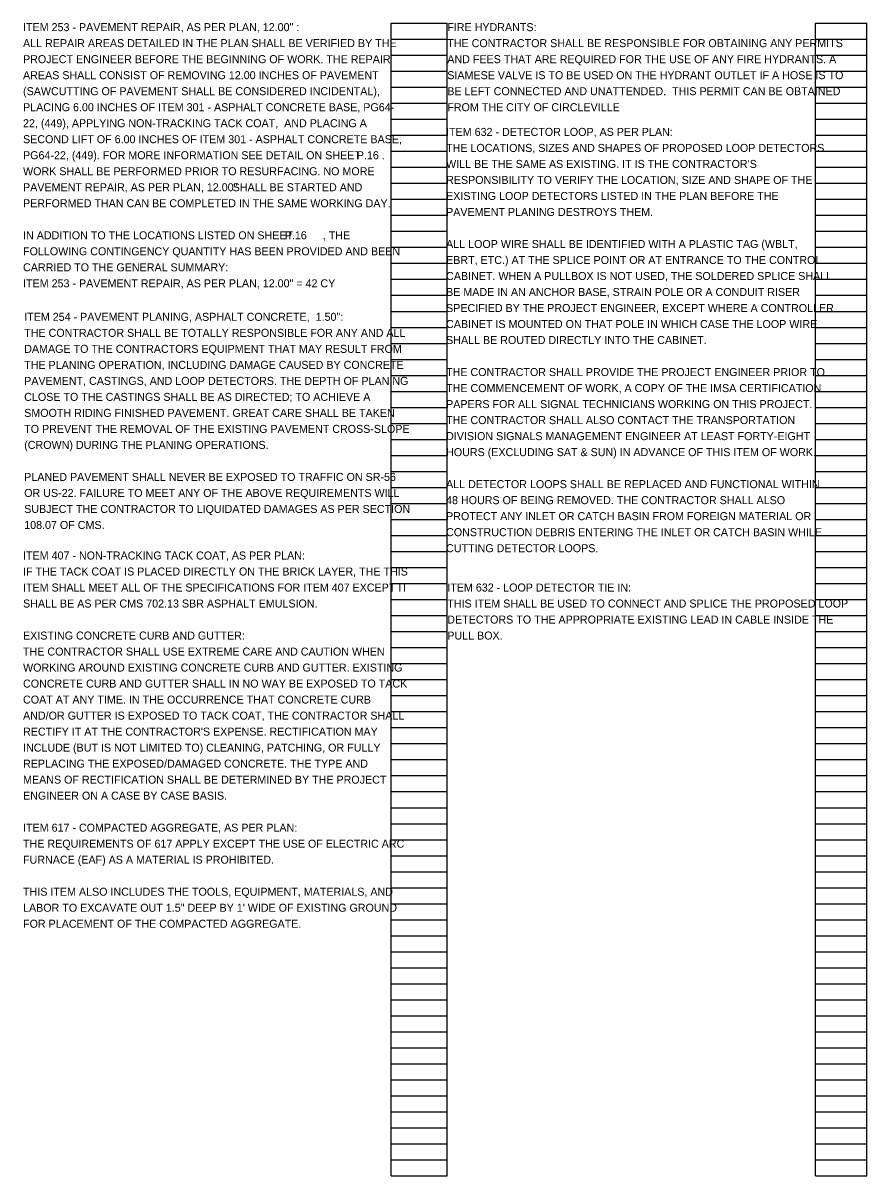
# Model space of a CAD drawing. Extents: x 28776.5 to 28808.5, y 9178.8 to 9230.7.
# Drawn here: x 28793.77 to 28808.53, y 9210.58 to 9230.74 of the extents above; entities that cross this region are included whole.
import ezdxf

# ---------------------------------------------------------------- set-up
doc = ezdxf.new("R2010")
doc.units = 0
for name, color, linetype in [('Default', 7, 'Continuous'), ('SH_Data', 7, 'Continuous'), ('SH_Text', 7, 'Continuous')]:
    doc.layers.add(name, color=color, linetype=linetype)

msp = doc.modelspace()

# ---------------------------------------------------------------- linework, layer by layer
at = {"layer": 'SH_Data'}
for p, q in [((28800.209, 9210.582), (28800.209, 9230.742)), ((28800.209, 9230.742), (28801.189, 9230.742)), ((28801.189, 9210.582), (28801.189, 9230.742)), ((28807.629, 9210.582), (28807.629, 9230.742)), ((28807.629, 9230.742), (28808.529, 9230.742)), ((28808.529, 9210.582), (28808.529, 9230.742)), ((28800.209, 9230.462), (28801.189, 9230.462)), ((28807.629, 9230.462), (28808.529, 9230.462)), ((28800.209, 9230.182), (28801.189, 9230.182)), ((28807.629, 9230.182), (28808.529, 9230.182)), ((28800.209, 9229.902), (28801.189, 9229.902)), ((28807.629, 9229.902), (28808.529, 9229.902)), ((28800.209, 9229.622), (28801.189, 9229.622)), ((28807.629, 9229.622), (28808.529, 9229.622)), ((28800.209, 9229.342), (28801.189, 9229.342)), ((28807.629, 9229.342), (28808.529, 9229.342)), ((28800.209, 9229.062), (28801.189, 9229.062)), ((28807.629, 9229.062), (28808.529, 9229.062)), ((28800.209, 9228.782), (28801.189, 9228.782)), ((28807.629, 9228.782), (28808.529, 9228.782)), ((28800.209, 9228.502), (28801.189, 9228.502)), ((28807.629, 9228.502), (28808.529, 9228.502)), ((28800.209, 9228.222), (28801.189, 9228.222)), ((28807.629, 9228.222), (28808.529, 9228.222)), ((28800.209, 9227.942), (28801.189, 9227.942)), ((28807.629, 9227.942), (28808.529, 9227.942)), ((28800.209, 9227.662), (28801.189, 9227.662)), ((28807.629, 9227.662), (28808.529, 9227.662)), ((28800.209, 9227.382), (28801.189, 9227.382)), ((28807.629, 9227.382), (28808.529, 9227.382)), ((28800.209, 9227.102), (28801.189, 9227.102)), ((28807.629, 9227.102), (28808.529, 9227.102)), ((28800.209, 9226.822), (28801.189, 9226.822)), ((28807.629, 9226.822), (28808.529, 9226.822)), ((28800.209, 9226.542), (28801.189, 9226.542)), ((28807.629, 9226.542), (28808.529, 9226.542)), ((28800.209, 9226.262), (28801.189, 9226.262)), ((28807.629, 9226.262), (28808.529, 9226.262)), ((28800.209, 9225.982), (28801.189, 9225.982)), ((28807.629, 9225.982), (28808.529, 9225.982)), ((28800.209, 9225.702), (28801.189, 9225.702)), ((28807.629, 9225.702), (28808.529, 9225.702)), ((28800.209, 9225.422), (28801.189, 9225.422)), ((28807.629, 9225.422), (28808.529, 9225.422)), ((28800.209, 9225.142), (28801.189, 9225.142)), ((28807.629, 9225.142), (28808.529, 9225.142)), ((28800.209, 9224.862), (28801.189, 9224.862)), ((28807.629, 9224.862), (28808.529, 9224.862)), ((28800.209, 9224.582), (28801.189, 9224.582)), ((28807.629, 9224.582), (28808.529, 9224.582)), ((28800.209, 9224.302), (28801.189, 9224.302)), ((28807.629, 9224.302), (28808.529, 9224.302)), ((28800.209, 9224.022), (28801.189, 9224.022)), ((28807.629, 9224.022), (28808.529, 9224.022)), ((28800.209, 9223.742), (28801.189, 9223.742)), ((28807.629, 9223.742), (28808.529, 9223.742)), ((28800.209, 9223.462), (28801.189, 9223.462)), ((28807.629, 9223.462), (28808.529, 9223.462)), ((28800.209, 9223.182), (28801.189, 9223.182)), ((28807.629, 9223.182), (28808.529, 9223.182)), ((28800.209, 9222.902), (28801.189, 9222.902)), ((28807.629, 9222.902), (28808.529, 9222.902)), ((28800.209, 9222.622), (28801.189, 9222.622)), ((28807.629, 9222.622), (28808.529, 9222.622)), ((28800.209, 9222.342), (28801.189, 9222.342)), ((28807.629, 9222.342), (28808.529, 9222.342)), ((28800.209, 9222.062), (28801.189, 9222.062)), ((28807.629, 9222.062), (28808.529, 9222.062)), ((28800.209, 9221.782), (28801.189, 9221.782)), ((28807.629, 9221.782), (28808.529, 9221.782)), ((28800.209, 9221.502), (28801.189, 9221.502)), ((28807.629, 9221.502), (28808.529, 9221.502)), ((28800.209, 9221.222), (28801.189, 9221.222)), ((28807.629, 9221.222), (28808.529, 9221.222)), ((28800.209, 9220.942), (28801.189, 9220.942)), ((28807.629, 9220.942), (28808.529, 9220.942)), ((28800.209, 9220.662), (28801.189, 9220.662)), ((28807.629, 9220.662), (28808.529, 9220.662)), ((28800.209, 9220.382), (28801.189, 9220.382)), ((28807.629, 9220.382), (28808.529, 9220.382)), ((28800.209, 9220.102), (28801.189, 9220.102)), ((28807.629, 9220.102), (28808.529, 9220.102)), ((28800.209, 9219.822), (28801.189, 9219.822)), ((28807.629, 9219.822), (28808.529, 9219.822)), ((28800.209, 9219.542), (28801.189, 9219.542)), ((28807.629, 9219.542), (28808.529, 9219.542)), ((28800.209, 9219.262), (28801.189, 9219.262)), ((28807.629, 9219.262), (28808.529, 9219.262)), ((28800.209, 9218.982), (28801.189, 9218.982)), ((28807.629, 9218.982), (28808.529, 9218.982)), ((28800.209, 9218.702), (28801.189, 9218.702)), ((28807.629, 9218.702), (28808.529, 9218.702)), ((28800.209, 9218.422), (28801.189, 9218.422)), ((28807.629, 9218.422), (28808.529, 9218.422)), ((28800.209, 9218.142), (28801.189, 9218.142)), ((28807.629, 9218.142), (28808.529, 9218.142)), ((28800.209, 9217.862), (28801.189, 9217.862)), ((28807.629, 9217.862), (28808.529, 9217.862)), ((28800.209, 9217.582), (28801.189, 9217.582)), ((28807.629, 9217.582), (28808.529, 9217.582)), ((28800.209, 9217.302), (28801.189, 9217.302)), ((28807.629, 9217.302), (28808.529, 9217.302)), ((28800.209, 9217.022), (28801.189, 9217.022)), ((28807.629, 9217.022), (28808.529, 9217.022)), ((28800.209, 9216.742), (28801.189, 9216.742)), ((28807.629, 9216.742), (28808.529, 9216.742)), ((28800.209, 9216.462), (28801.189, 9216.462)), ((28807.629, 9216.462), (28808.529, 9216.462)), ((28800.209, 9216.182), (28801.189, 9216.182)), ((28807.629, 9216.182), (28808.529, 9216.182)), ((28800.209, 9215.902), (28801.189, 9215.902)), ((28807.629, 9215.902), (28808.529, 9215.902)), ((28800.209, 9215.622), (28801.189, 9215.622)), ((28807.629, 9215.622), (28808.529, 9215.622)), ((28800.209, 9215.342), (28801.189, 9215.342)), ((28807.629, 9215.342), (28808.529, 9215.342)), ((28800.209, 9215.062), (28801.189, 9215.062)), ((28807.629, 9215.062), (28808.529, 9215.062)), ((28800.209, 9214.782), (28801.189, 9214.782)), ((28807.629, 9214.782), (28808.529, 9214.782)), ((28800.209, 9214.502), (28801.189, 9214.502)), ((28807.629, 9214.502), (28808.529, 9214.502)), ((28800.209, 9214.222), (28801.189, 9214.222)), ((28807.629, 9214.222), (28808.529, 9214.222)), ((28800.209, 9213.942), (28801.189, 9213.942)), ((28807.629, 9213.942), (28808.529, 9213.942)), ((28800.209, 9213.662), (28801.189, 9213.662)), ((28807.629, 9213.662), (28808.529, 9213.662)), ((28800.209, 9213.382), (28801.189, 9213.382)), ((28807.629, 9213.382), (28808.529, 9213.382)), ((28800.209, 9213.102), (28801.189, 9213.102)), ((28807.629, 9213.102), (28808.529, 9213.102)), ((28800.209, 9212.822), (28801.189, 9212.822)), ((28807.629, 9212.822), (28808.529, 9212.822)), ((28800.209, 9212.542), (28801.189, 9212.542)), ((28807.629, 9212.542), (28808.529, 9212.542)), ((28800.209, 9212.262), (28801.189, 9212.262)), ((28807.629, 9212.262), (28808.529, 9212.262)), ((28800.209, 9211.982), (28801.189, 9211.982)), ((28807.629, 9211.982), (28808.529, 9211.982)), ((28800.209, 9211.702), (28801.189, 9211.702)), ((28807.629, 9211.702), (28808.529, 9211.702)), ((28800.209, 9211.422), (28801.189, 9211.422)), ((28807.629, 9211.422), (28808.529, 9211.422)), ((28800.209, 9211.142), (28801.189, 9211.142)), ((28807.629, 9211.142), (28808.529, 9211.142)), ((28800.209, 9210.862), (28801.189, 9210.862)), ((28807.629, 9210.862), (28808.529, 9210.862)), ((28800.209, 9210.582), (28801.189, 9210.582)), ((28807.629, 9210.582), (28808.529, 9210.582))]:
    msp.add_line(p, q, dxfattribs=at)

# ---------------------------------------------------------------- texts
at = {"layer": 'Default'}
for s, p in [('ITEM 254 - PAVEMENT PLANING, ASPHALT CONCRETE,  1.50":', (28793.789, 9225.536)), ('THE CONTRACTOR SHALL BE TOTALLY RESPONSIBLE FOR ANY AND ALL ', (28793.789, 9225.256)), ('DAMAGE TO THE CONTRACTORS EQUIPMENT THAT MAY RESULT FROM ', (28793.789, 9224.976)), ('THE PLANING OPERATION, INCLUDING DAMAGE CAUSED BY CONCRETE ', (28793.789, 9224.696)), ('PAVEMENT, CASTINGS, AND LOOP DETECTORS. THE DEPTH OF PLANING ', (28793.789, 9224.416)), ('CLOSE TO THE CASTINGS SHALL BE AS DIRECTED; TO ACHIEVE A ', (28793.789, 9224.136)), ('SMOOTH RIDING FINISHED PAVEMENT. GREAT CARE SHALL BE TAKEN ', (28793.789, 9223.856)), ('TO PREVENT THE REMOVAL OF THE EXISTING PAVEMENT CROSS-SLOPE ', (28793.789, 9223.576)), ('(CROWN) DURING THE PLANING OPERATIONS.', (28793.789, 9223.296)), ('PLANED PAVEMENT SHALL NEVER BE EXPOSED TO TRAFFIC ON SR-56 ', (28793.789, 9222.736)), ('OR US-22. FAILURE TO MEET ANY OF THE ABOVE REQUIREMENTS WILL ', (28793.789, 9222.456)), ('SUBJECT THE CONTRACTOR TO LIQUIDATED DAMAGES AS PER SECTION ', (28793.789, 9222.176)), ('108.07 OF CMS.', (28793.789, 9221.896))]:
    msp.add_text(s, height=0.14, dxfattribs=at).set_placement(p)
at = {"layer": 'SH_Text'}
for s, p in [('ITEM 253 - PAVEMENT REPAIR, AS PER PLAN, 12.00" :', (28793.769, 9230.602)), ('FIRE HYDRANTS:', (28801.189, 9230.602)), ('ALL REPAIR AREAS DETAILED IN THE PLAN SHALL BE VERIFIED BY THE ', (28793.769, 9230.322)), ('THE CONTRACTOR SHALL BE RESPONSIBLE FOR OBTAINING ANY PERMITS ', (28801.189, 9230.322)), ('PROJECT ENGINEER BEFORE THE BEGINNING OF WORK. THE REPAIR ', (28793.769, 9230.042)), ('AND FEES THAT ARE REQUIRED FOR THE USE OF ANY FIRE HYDRANTS. A ', (28801.189, 9230.042)), ('AREAS SHALL CONSIST OF REMOVING 12.00 INCHES OF PAVEMENT ', (28793.769, 9229.762)), ('SIAMESE VALVE IS TO BE USED ON THE HYDRANT OUTLET IF A HOSE IS TO ', (28801.189, 9229.762)), ('(SAWCUTTING OF PAVEMENT SHALL BE CONSIDERED INCIDENTAL), ', (28793.769, 9229.482)), ('BE LEFT CONNECTED AND UNATTENDED.  THIS PERMIT CAN BE OBTAINED ', (28801.189, 9229.482)), ('PLACING 6.00 INCHES OF ITEM 301 - ASPHALT CONCRETE BASE, PG64-', (28793.769, 9229.202)), ('FROM THE CITY OF CIRCLEVILLE', (28801.189, 9229.202)), ('22, (449), APPLYING NON-TRACKING TACK COAT,  AND PLACING A ', (28793.769, 9228.922)), ('ITEM 632 - DETECTOR LOOP, AS PER PLAN:', (28801.168, 9228.77)), ('SECOND LIFT OF 6.00 INCHES OF ITEM 301 - ASPHALT CONCRETE BASE, ', (28793.769, 9228.642)), ('THE LOCATIONS, SIZES AND SHAPES OF PROPOSED LOOP DETECTORS ', (28801.168, 9228.49)), ('PG64-22, (449). FOR MORE INFORMATION SEE DETAIL ON SHEET', (28793.769, 9228.362)), ('P.16', (28799.606, 9228.362)), ('WORK SHALL BE PERFORMED PRIOR TO RESURFACING. NO MORE ', (28793.769, 9228.082)), ('          . ', (28799.52, 9228.362)), ("WILL BE THE SAME AS EXISTING. IT IS THE CONTRACTOR'S ", (28801.168, 9228.21)), ('RESPONSIBILITY TO VERIFY THE LOCATION, SIZE AND SHAPE OF THE ', (28801.168, 9227.93)), ('PAVEMENT REPAIR, AS PER PLAN, 12.00"', (28793.769, 9227.802)), ('SHALL BE STARTED AND ', (28797.435, 9227.802)), ('EXISTING LOOP DETECTORS LISTED IN THE PLAN BEFORE THE ', (28801.168, 9227.65)), ('PERFORMED THAN CAN BE COMPLETED IN THE SAME WORKING DAY.', (28793.769, 9227.522)), ('PAVEMENT PLANING DESTROYS THEM. ', (28801.168, 9227.37)), ('IN ADDITION TO THE LOCATIONS LISTED ON SHEET          , THE ', (28793.769, 9226.962)), ('P.16', (28798.346, 9226.962)), ('FOLLOWING CONTINGENCY QUANTITY HAS BEEN PROVIDED AND BEEN ', (28793.769, 9226.682)), ('ALL LOOP WIRE SHALL BE IDENTIFIED WITH A PLASTIC TAG (WBLT, ', (28801.168, 9226.81)), ('EBRT, ETC.) AT THE SPLICE POINT OR AT ENTRANCE TO THE CONTROL ', (28801.168, 9226.53)), ('CARRIED TO THE GENERAL SUMMARY:', (28793.769, 9226.402)), ('CABINET. WHEN A PULLBOX IS NOT USED, THE SOLDERED SPLICE SHALL ', (28801.168, 9226.25)), ('ITEM 253 - PAVEMENT REPAIR, AS PER PLAN, 12.00" = 42 CY', (28793.769, 9226.122)), ('BE MADE IN AN ANCHOR BASE, STRAIN POLE OR A CONDUIT RISER ', (28801.168, 9225.97)), ('SPECIFIED BY THE PROJECT ENGINEER, EXCEPT WHERE A CONTROLLER ', (28801.168, 9225.69)), ('CABINET IS MOUNTED ON THAT POLE IN WHICH CASE THE LOOP WIRE ', (28801.168, 9225.41)), ('SHALL BE ROUTED DIRECTLY INTO THE CABINET. ', (28801.168, 9225.13)), ('THE CONTRACTOR SHALL PROVIDE THE PROJECT ENGINEER PRIOR TO ', (28801.168, 9224.57)), ('THE COMMENCEMENT OF WORK, A COPY OF THE IMSA CERTIFICATION ', (28801.168, 9224.29)), ('PAPERS FOR ALL SIGNAL TECHNICIANS WORKING ON THIS PROJECT. ', (28801.168, 9224.01)), ('THE CONTRACTOR SHALL ALSO CONTACT THE TRANSPORTATION ', (28801.168, 9223.73)), ('DIVISION SIGNALS MANAGEMENT ENGINEER AT LEAST FORTY-EIGHT ', (28801.168, 9223.45)), ('HOURS (EXCLUDING SAT & SUN) IN ADVANCE OF THIS ITEM OF WORK. ', (28801.168, 9223.17)), ('ALL DETECTOR LOOPS SHALL BE REPLACED AND FUNCTIONAL WITHIN ', (28801.168, 9222.61)), ('48 HOURS OF BEING REMOVED. THE CONTRACTOR SHALL ALSO ', (28801.168, 9222.33)), ('PROTECT ANY INLET OR CATCH BASIN FROM FOREIGN MATERIAL OR ', (28801.168, 9222.05)), ('CONSTRUCTION DEBRIS ENTERING THE INLET OR CATCH BASIN WHILE ', (28801.168, 9221.77)), ('CUTTING DETECTOR LOOPS.', (28801.168, 9221.49)), ('ITEM 407 - NON-TRACKING TACK COAT, AS PER PLAN:', (28793.769, 9221.362)), ('IF THE TACK COAT IS PLACED DIRECTLY ON THE BRICK LAYER, THE THIS ', (28793.769, 9221.082)), ('ITEM SHALL MEET ALL OF THE SPECIFICATIONS FOR ITEM 407 EXCEPT IT ', (28793.769, 9220.802)), ('ITEM 632 - LOOP DETECTOR TIE IN:', (28801.189, 9220.802)), ('SHALL BE AS PER CMS 702.13 SBR ASPHALT EMULSION.', (28793.769, 9220.522)), ('THIS ITEM SHALL BE USED TO CONNECT AND SPLICE THE PROPOSED LOOP ', (28801.189, 9220.522)), ('DETECTORS TO THE APPROPRIATE EXISTING LEAD IN CABLE INSIDE THE ', (28801.189, 9220.242)), ('EXISTING CONCRETE CURB AND GUTTER:', (28793.769, 9219.962)), ('PULL BOX. ', (28801.189, 9219.962)), ('THE CONTRACTOR SHALL USE EXTREME CARE AND CAUTION WHEN ', (28793.769, 9219.682)), ('WORKING AROUND EXISTING CONCRETE CURB AND GUTTER. EXISTING ', (28793.769, 9219.402)), ('CONCRETE CURB AND GUTTER SHALL IN NO WAY BE EXPOSED TO TACK ', (28793.769, 9219.122)), ('COAT AT ANY TIME. IN THE OCCURRENCE THAT CONCRETE CURB ', (28793.769, 9218.842)), ('AND/OR GUTTER IS EXPOSED TO TACK COAT, THE CONTRACTOR SHALL ', (28793.769, 9218.562)), ("RECTIFY IT AT THE CONTRACTOR'S EXPENSE. RECTIFICATION MAY ", (28793.769, 9218.282)), ('INCLUDE (BUT IS NOT LIMITED TO) CLEANING, PATCHING, OR FULLY ', (28793.769, 9218.002)), ('REPLACING THE EXPOSED/DAMAGED CONCRETE. THE TYPE AND ', (28793.769, 9217.722)), ('MEANS OF RECTIFICATION SHALL BE DETERMINED BY THE PROJECT ', (28793.769, 9217.442)), ('ENGINEER ON A CASE BY CASE BASIS. ', (28793.769, 9217.162)), ('ITEM 617 - COMPACTED AGGREGATE, AS PER PLAN:', (28793.769, 9216.602)), ('THE REQUIREMENTS OF 617 APPLY EXCEPT THE USE OF ELECTRIC ARC ', (28793.769, 9216.322)), ('FURNACE (EAF) AS A MATERIAL IS PROHIBITED. ', (28793.769, 9216.042)), ('THIS ITEM ALSO INCLUDES THE TOOLS, EQUIPMENT, MATERIALS, AND ', (28793.769, 9215.482)), ('LABOR TO EXCAVATE OUT 1.5" DEEP BY 1\' WIDE OF EXISTING GROUND ', (28793.769, 9215.202)), ('FOR PLACEMENT OF THE COMPACTED AGGREGATE.', (28793.769, 9214.922))]:
    msp.add_text(s, height=0.14, dxfattribs=at).set_placement(p)

doc.saveas('drawing.dxf')
